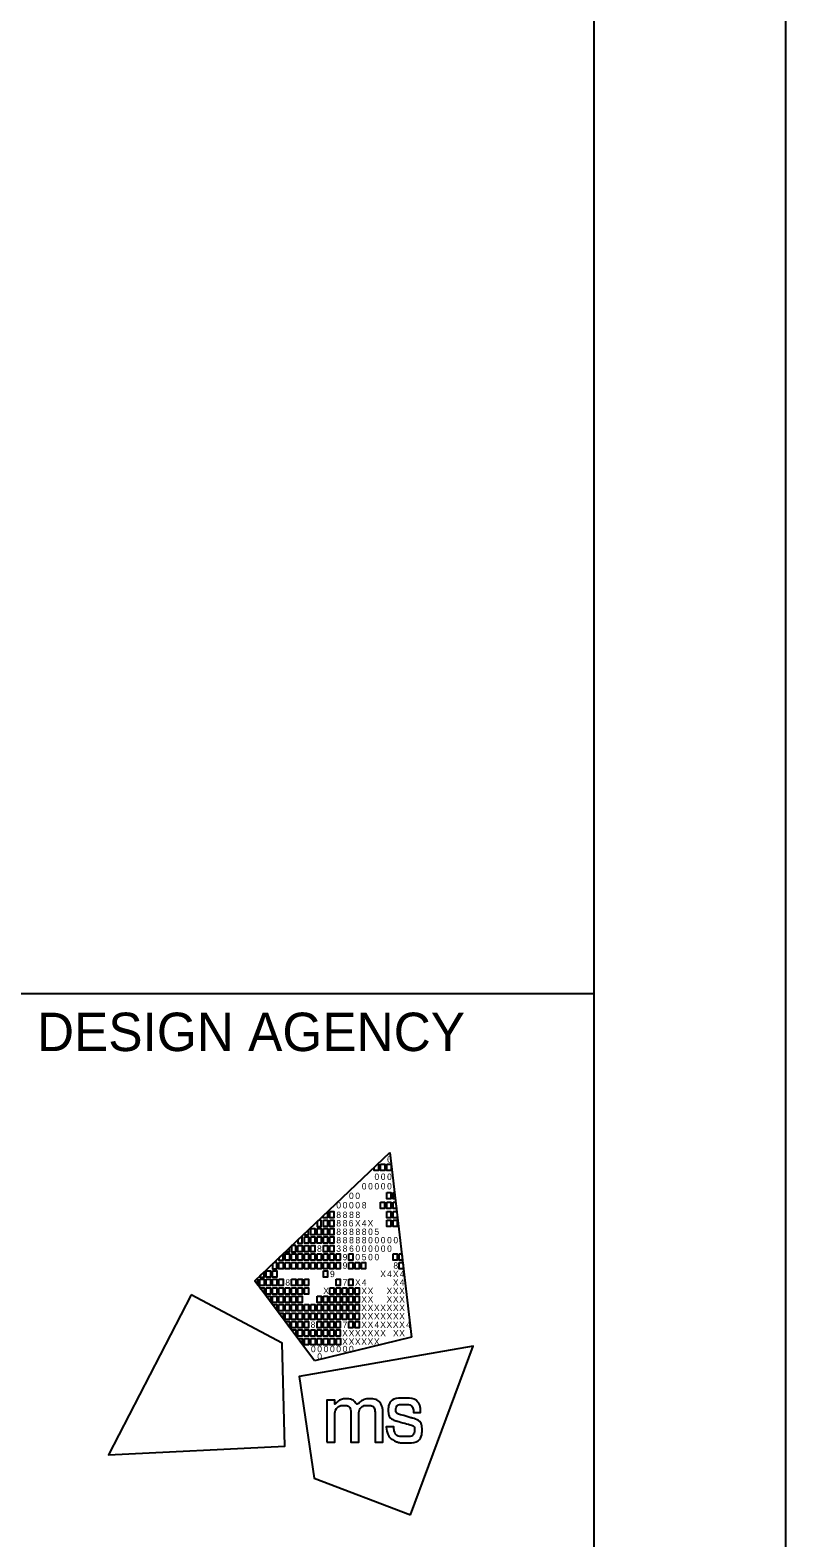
# Model space of a CAD drawing. Extents: x 0 to 34, y -1.2 to 22.
# Drawn here: x 32.032 to 34, y 3.582 to 7.509 of the extents above; entities that cross this region are included whole.
import ezdxf

# ---------------------------------------------------------------- set-up
doc = ezdxf.new("R2010")
doc.units = 0
for name, color, linetype in [('SH_Border', 7, 'Continuous'), ('SH_Cut_Line', 7, 'Continuous'), ('SH_Data', 7, 'Continuous'), ('SH_Text', 7, 'Continuous')]:
    doc.layers.add(name, color=color, linetype=linetype)

msp = doc.modelspace()

# ---------------------------------------------------------------- linework, layer by layer
at = {"layer": 'SH_Border'}
msp.add_line((32, 5), (33.5, 5), dxfattribs=at)
msp.add_lwpolyline([(1.5, 21.5), (33.5, 21.5), (33.5, 0.5), (1.5, 0.5)], close=True, dxfattribs=at)
at = {"layer": 'SH_Cut_Line'}
msp.add_lwpolyline([(0, 0), (34, 0), (34, 22), (0, 22)], close=True, dxfattribs=at)
at = {"layer": 'SH_Data'}
msp.add_line((32.75, 4), (32.75, 4), dxfattribs=at)
at = {"layer": 'SH_Text'}
for p, q in [((32.6175, 4.2519), (32.9688, 4.5861)), ((32.9688, 4.5861), (32.9688, 4.5861)), ((32.9688, 4.5861), (33.0253, 4.1052)), ((32.773, 4.043), (32.6175, 4.2519)), ((33.0253, 4.1052), (32.773, 4.043))]:
    msp.add_line(p, q, dxfattribs=at)
for points in [[(32.9279, 4.5472), (32.9369, 4.5558), (32.9389, 4.5558), (32.9389, 4.5393), (32.9279, 4.5393)], [(32.9444, 4.5558), (32.9554, 4.5558), (32.9554, 4.5393), (32.9444, 4.5393)], [(32.9609, 4.5558), (32.9719, 4.5558), (32.9719, 4.5393), (32.9609, 4.5393)], [(32.9606, 4.4815), (32.9716, 4.4815), (32.9716, 4.465), (32.9606, 4.465)], [(32.9771, 4.4815), (32.9811, 4.4815), (32.983, 4.465), (32.9771, 4.465)], [(32.9441, 4.4567), (32.9551, 4.4567), (32.9551, 4.4402), (32.9441, 4.4402)], [(32.9606, 4.4567), (32.9716, 4.4567), (32.9716, 4.4402), (32.9606, 4.4402)], [(32.9771, 4.4567), (32.984, 4.4567), (32.9859, 4.4402), (32.9771, 4.4402)], [(32.7953, 4.4211), (32.8064, 4.4316), (32.8064, 4.4154), (32.7953, 4.4154)], [(32.7958, 4.4099), (32.8068, 4.4099), (32.8068, 4.3934), (32.7958, 4.3934)], [(32.8123, 4.4319), (32.8233, 4.4319), (32.8233, 4.4154), (32.8123, 4.4154)], [(32.8123, 4.4099), (32.8233, 4.4099), (32.8233, 4.3934), (32.8123, 4.3934)], [(32.9606, 4.4319), (32.9716, 4.4319), (32.9716, 4.4154), (32.9606, 4.4154)], [(32.9606, 4.4099), (32.9716, 4.4099), (32.9716, 4.3934), (32.9606, 4.3934)], [(32.9771, 4.4319), (32.9869, 4.4319), (32.9881, 4.4218), (32.9881, 4.4154), (32.9771, 4.4154)], [(32.9771, 4.4099), (32.9881, 4.4099), (32.9881, 4.3934), (32.9771, 4.3934)], [(32.7462, 4.3659), (32.7572, 4.3659), (32.7572, 4.3494), (32.7462, 4.3494)], [(32.7627, 4.3879), (32.7737, 4.3879), (32.7737, 4.3714), (32.7627, 4.3714)], [(32.7627, 4.3659), (32.7737, 4.3659), (32.7737, 4.3494), (32.7627, 4.3494)], [(32.7793, 4.3879), (32.7903, 4.3879), (32.7903, 4.3714), (32.7793, 4.3714)], [(32.7793, 4.3659), (32.7903, 4.3659), (32.7903, 4.3494), (32.7793, 4.3494)], [(32.7958, 4.3879), (32.8068, 4.3879), (32.8068, 4.3714), (32.7958, 4.3714)], [(32.7958, 4.3659), (32.8068, 4.3659), (32.8068, 4.3494), (32.7958, 4.3494)], [(32.8123, 4.3879), (32.8233, 4.3879), (32.8233, 4.3714), (32.8123, 4.3714)], [(32.8123, 4.3659), (32.8233, 4.3659), (32.8233, 4.3494), (32.8123, 4.3494)], [(32.6967, 4.3218), (32.7077, 4.3218), (32.7077, 4.3053), (32.6967, 4.3053)], [(32.7132, 4.3218), (32.7242, 4.3218), (32.7242, 4.3053), (32.7132, 4.3053)], [(32.7297, 4.3439), (32.7407, 4.3439), (32.7407, 4.3273), (32.7297, 4.3273)], [(32.7297, 4.3218), (32.7407, 4.3218), (32.7407, 4.3053), (32.7297, 4.3053)], [(32.7462, 4.3439), (32.7572, 4.3439), (32.7572, 4.3273), (32.7462, 4.3273)], [(32.7462, 4.3218), (32.7572, 4.3218), (32.7572, 4.3053), (32.7462, 4.3053)], [(32.7627, 4.3439), (32.7737, 4.3439), (32.7737, 4.3273), (32.7627, 4.3273)], [(32.7627, 4.3218), (32.7737, 4.3218), (32.7737, 4.3053), (32.7627, 4.3053)], [(32.7793, 4.3218), (32.7903, 4.3218), (32.7903, 4.3053), (32.7793, 4.3053)], [(32.7958, 4.3439), (32.8068, 4.3439), (32.8068, 4.3273), (32.7958, 4.3273)], [(32.7958, 4.3218), (32.8068, 4.3218), (32.8068, 4.3053), (32.7958, 4.3053)], [(32.8123, 4.3439), (32.8233, 4.3439), (32.8233, 4.3273), (32.8123, 4.3273)], [(32.8123, 4.3218), (32.8233, 4.3218), (32.8233, 4.3053), (32.8123, 4.3053)], [(32.8288, 4.3218), (32.8398, 4.3218), (32.8398, 4.3053), (32.8288, 4.3053)], [(32.8618, 4.3218), (32.8728, 4.3218), (32.8728, 4.3053), (32.8618, 4.3053)], [(32.9771, 4.3218), (32.9881, 4.3218), (32.9881, 4.3053), (32.9771, 4.3053)], [(32.9935, 4.3218), (32.9998, 4.3218), (33.0018, 4.3053), (32.9935, 4.3053)], [(32.6802, 4.2998), (32.6912, 4.2998), (32.6912, 4.2833), (32.6802, 4.2833)], [(32.6967, 4.2998), (32.7077, 4.2998), (32.7077, 4.2833), (32.6967, 4.2833)], [(32.7132, 4.2998), (32.7242, 4.2998), (32.7242, 4.2833), (32.7132, 4.2833)], [(32.7297, 4.2998), (32.7407, 4.2998), (32.7407, 4.2833), (32.7297, 4.2833)], [(32.7462, 4.2998), (32.7572, 4.2998), (32.7572, 4.2833), (32.7462, 4.2833)], [(32.7627, 4.2998), (32.7737, 4.2998), (32.7737, 4.2833), (32.7627, 4.2833)], [(32.7793, 4.2998), (32.7903, 4.2998), (32.7903, 4.2833), (32.7793, 4.2833)], [(32.7958, 4.2998), (32.8068, 4.2998), (32.8068, 4.2833), (32.7958, 4.2833)], [(32.8123, 4.2998), (32.8233, 4.2998), (32.8233, 4.2833), (32.8123, 4.2833)], [(32.8288, 4.2998), (32.8398, 4.2998), (32.8398, 4.2833), (32.8288, 4.2833)], [(32.8618, 4.2998), (32.8728, 4.2998), (32.8728, 4.2833), (32.8618, 4.2833)], [(32.8783, 4.2998), (32.8893, 4.2998), (32.8893, 4.2833), (32.8783, 4.2833)], [(32.8947, 4.2998), (32.9057, 4.2998), (32.9057, 4.2833), (32.8947, 4.2833)], [(32.9935, 4.2998), (33.0024, 4.2998), (33.0044, 4.2833), (32.9935, 4.2833)], [(32.6306, 4.2558), (32.6416, 4.2558), (32.6416, 4.2393), (32.6306, 4.2393)], [(32.6471, 4.2778), (32.6581, 4.2778), (32.6581, 4.2613), (32.6471, 4.2613)], [(32.6471, 4.2558), (32.6581, 4.2558), (32.6581, 4.2393), (32.6471, 4.2393)], [(32.6637, 4.2778), (32.6747, 4.2778), (32.6747, 4.2613), (32.6637, 4.2613)], [(32.6637, 4.2558), (32.6747, 4.2558), (32.6747, 4.2393), (32.6637, 4.2393)], [(32.6802, 4.2558), (32.6912, 4.2558), (32.6912, 4.2393), (32.6802, 4.2393)], [(32.7132, 4.2558), (32.7242, 4.2558), (32.7242, 4.2393), (32.7132, 4.2393)], [(32.7297, 4.2558), (32.7407, 4.2558), (32.7407, 4.2393), (32.7297, 4.2393)], [(32.7462, 4.2558), (32.7572, 4.2558), (32.7572, 4.2393), (32.7462, 4.2393)], [(32.7958, 4.2778), (32.8068, 4.2778), (32.8068, 4.2613), (32.7958, 4.2613)], [(32.8288, 4.2558), (32.8398, 4.2558), (32.8398, 4.2393), (32.8288, 4.2393)], [(32.8618, 4.2558), (32.8728, 4.2558), (32.8728, 4.2393), (32.8618, 4.2393)], [(32.6306, 4.2338), (32.6416, 4.2338), (32.6416, 4.22)], [(32.6471, 4.2338), (32.6581, 4.2338), (32.6581, 4.2173), (32.6471, 4.2173)], [(32.6471, 4.2117), (32.6581, 4.2117), (32.6581, 4.198)], [(32.6637, 4.2338), (32.6747, 4.2338), (32.6747, 4.2173), (32.6637, 4.2173)], [(32.6637, 4.2117), (32.6747, 4.2117), (32.6747, 4.1952), (32.6637, 4.1952)], [(32.6802, 4.2338), (32.6912, 4.2338), (32.6912, 4.2173), (32.6802, 4.2173)], [(32.6802, 4.2117), (32.6912, 4.2117), (32.6912, 4.1952), (32.6802, 4.1952)], [(32.6967, 4.2338), (32.7077, 4.2338), (32.7077, 4.2173), (32.6967, 4.2173)], [(32.6967, 4.2117), (32.7077, 4.2117), (32.7077, 4.1952), (32.6967, 4.1952)], [(32.7132, 4.2338), (32.7242, 4.2338), (32.7242, 4.2173), (32.7132, 4.2173)], [(32.7132, 4.2117), (32.7242, 4.2117), (32.7242, 4.1952), (32.7132, 4.1952)], [(32.7297, 4.2338), (32.7407, 4.2338), (32.7407, 4.2173), (32.7297, 4.2173)], [(32.7297, 4.2117), (32.7407, 4.2117), (32.7407, 4.1952), (32.7297, 4.1952)], [(32.7462, 4.2338), (32.7572, 4.2338), (32.7572, 4.2173), (32.7462, 4.2173)], [(32.7793, 4.2117), (32.7903, 4.2117), (32.7903, 4.1952), (32.7793, 4.1952)], [(32.7958, 4.2117), (32.8068, 4.2117), (32.8068, 4.1952), (32.7958, 4.1952)], [(32.8123, 4.2338), (32.8233, 4.2338), (32.8233, 4.2173), (32.8123, 4.2173)], [(32.8123, 4.2117), (32.8233, 4.2117), (32.8233, 4.1952), (32.8123, 4.1952)], [(32.8288, 4.2338), (32.8398, 4.2338), (32.8398, 4.2173), (32.8288, 4.2173)], [(32.8288, 4.2117), (32.8398, 4.2117), (32.8398, 4.1952), (32.8288, 4.1952)], [(32.8453, 4.2338), (32.8563, 4.2338), (32.8563, 4.2173), (32.8453, 4.2173)], [(32.8453, 4.2117), (32.8563, 4.2117), (32.8563, 4.1952), (32.8453, 4.1952)], [(32.8618, 4.2338), (32.8728, 4.2338), (32.8728, 4.2173), (32.8618, 4.2173)], [(32.8618, 4.2117), (32.8728, 4.2117), (32.8728, 4.1952), (32.8618, 4.1952)], [(32.8783, 4.2338), (32.8893, 4.2338), (32.8893, 4.2173), (32.8783, 4.2173)], [(32.8783, 4.2117), (32.8893, 4.2117), (32.8893, 4.1952), (32.8783, 4.1952)], [(32.6637, 4.1897), (32.6747, 4.1897), (32.6747, 4.176)], [(32.6747, 4.1897), (32.6747, 4.1897), (32.6747, 4.1897)], [(32.6802, 4.1897), (32.6912, 4.1897), (32.6912, 4.1732), (32.6802, 4.1732)], [(32.6802, 4.1677), (32.6912, 4.1677), (32.6912, 4.154)], [(32.6967, 4.1897), (32.7077, 4.1897), (32.7077, 4.1732), (32.6967, 4.1732)], [(32.6967, 4.1677), (32.7077, 4.1677), (32.7077, 4.1512), (32.6967, 4.1512)], [(32.7132, 4.1897), (32.7242, 4.1897), (32.7242, 4.1732), (32.7132, 4.1732)], [(32.7132, 4.1677), (32.7242, 4.1677), (32.7242, 4.1512), (32.7132, 4.1512)], [(32.7297, 4.1897), (32.7407, 4.1897), (32.7407, 4.1732), (32.7297, 4.1732)], [(32.7297, 4.1677), (32.7407, 4.1677), (32.7407, 4.1512), (32.7297, 4.1512)], [(32.7462, 4.1897), (32.7572, 4.1897), (32.7572, 4.1732), (32.7462, 4.1732)], [(32.7462, 4.1677), (32.7572, 4.1677), (32.7572, 4.1512), (32.7462, 4.1512)], [(32.7627, 4.1897), (32.7737, 4.1897), (32.7737, 4.1732), (32.7627, 4.1732)], [(32.7627, 4.1677), (32.7737, 4.1677), (32.7737, 4.1512), (32.7627, 4.1512)], [(32.7793, 4.1897), (32.7903, 4.1897), (32.7903, 4.1732), (32.7793, 4.1732)], [(32.7793, 4.1677), (32.7903, 4.1677), (32.7903, 4.1512), (32.7793, 4.1512)], [(32.7958, 4.1897), (32.8068, 4.1897), (32.8068, 4.1732), (32.7958, 4.1732)], [(32.7958, 4.1677), (32.8068, 4.1677), (32.8068, 4.1512), (32.7958, 4.1512)], [(32.8123, 4.1897), (32.8233, 4.1897), (32.8233, 4.1732), (32.8123, 4.1732)], [(32.8123, 4.1677), (32.8233, 4.1677), (32.8233, 4.1512), (32.8123, 4.1512)], [(32.8288, 4.1897), (32.8398, 4.1897), (32.8398, 4.1732), (32.8288, 4.1732)], [(32.8288, 4.1677), (32.8398, 4.1677), (32.8398, 4.1512), (32.8288, 4.1512)], [(32.8453, 4.1897), (32.8563, 4.1897), (32.8563, 4.1732), (32.8453, 4.1732)], [(32.8453, 4.1677), (32.8563, 4.1677), (32.8563, 4.1512), (32.8453, 4.1512)], [(32.8618, 4.1897), (32.8728, 4.1897), (32.8728, 4.1732), (32.8618, 4.1732)], [(32.8618, 4.1677), (32.8728, 4.1677), (32.8728, 4.1512), (32.8618, 4.1512)], [(32.8783, 4.1897), (32.8893, 4.1897), (32.8893, 4.1732), (32.8783, 4.1732)], [(32.8783, 4.1677), (32.8893, 4.1677), (32.8893, 4.1512), (32.8783, 4.1512)], [(32.7077, 4.1305), (32.6965, 4.1457), (32.7077, 4.1457)], [(32.7132, 4.1457), (32.7242, 4.1457), (32.7242, 4.1292), (32.7132, 4.1292)], [(32.724, 4.1082), (32.7132, 4.1237), (32.7242, 4.1237)], [(32.7297, 4.1457), (32.7407, 4.1457), (32.7407, 4.1292), (32.7297, 4.1292)], [(32.7297, 4.1237), (32.7407, 4.1237), (32.7407, 4.1072), (32.7297, 4.1072)], [(32.7462, 4.1457), (32.7572, 4.1457), (32.7572, 4.1292), (32.7462, 4.1292)], [(32.7462, 4.1237), (32.7572, 4.1237), (32.7572, 4.1072), (32.7462, 4.1072)], [(32.7627, 4.1237), (32.7737, 4.1237), (32.7737, 4.1072), (32.7627, 4.1072)], [(32.7793, 4.1457), (32.7903, 4.1457), (32.7903, 4.1292), (32.7793, 4.1292)], [(32.7793, 4.1237), (32.7903, 4.1237), (32.7903, 4.1072), (32.7793, 4.1072)], [(32.7958, 4.1457), (32.8068, 4.1457), (32.8068, 4.1292), (32.7958, 4.1292)], [(32.7958, 4.1237), (32.8068, 4.1237), (32.8068, 4.1072), (32.7958, 4.1072)], [(32.8123, 4.1457), (32.8233, 4.1457), (32.8233, 4.1292), (32.8123, 4.1292)], [(32.8123, 4.1237), (32.8233, 4.1237), (32.8233, 4.1072), (32.8123, 4.1072)], [(32.8288, 4.1457), (32.8398, 4.1457), (32.8398, 4.1292), (32.8288, 4.1292)], [(32.8288, 4.1237), (32.8398, 4.1237), (32.8398, 4.1072), (32.8288, 4.1072)], [(32.8618, 4.1457), (32.8728, 4.1457), (32.8728, 4.1292), (32.8618, 4.1292)], [(32.8783, 4.1457), (32.8893, 4.1457), (32.8893, 4.1292), (32.8783, 4.1292)], [(32.7302, 4.1017), (32.7407, 4.1017), (32.7408, 4.0875)], [(32.7463, 4.1017), (32.7573, 4.1017), (32.7573, 4.0852), (32.7463, 4.0852)], [(32.763, 4.1017), (32.774, 4.1017), (32.774, 4.0852), (32.763, 4.0852)], [(32.7794, 4.1017), (32.7904, 4.1017), (32.7904, 4.0852), (32.7794, 4.0852)], [(32.796, 4.1017), (32.807, 4.1017), (32.807, 4.0852), (32.796, 4.0852)], [(32.8129, 4.1017), (32.8239, 4.1017), (32.8239, 4.0851), (32.8129, 4.0851)], [(32.8296, 4.1017), (32.8406, 4.1017), (32.8406, 4.0851), (32.8296, 4.0851)]]:
    msp.add_lwpolyline(points, close=True, dxfattribs=at)
for points in [[(32.7903, 4.4099), (32.7836, 4.4099), (32.7793, 4.4058), (32.7793, 4.3934), (32.7903, 4.3934), (32.7903, 4.4099)], [(32.7407, 4.3691), (32.7297, 4.3587), (32.7297, 4.3494), (32.7407, 4.3494), (32.7407, 4.3691)], [(32.7572, 4.3849), (32.7462, 4.3744), (32.7462, 4.3714), (32.7572, 4.3714), (32.7572, 4.3849)], [(32.6912, 4.322), (32.6802, 4.3115), (32.6802, 4.3053), (32.6912, 4.3053), (32.6912, 4.322)], [(32.7077, 4.3377), (32.6968, 4.3273), (32.7077, 4.3273), (32.7077, 4.3377)], [(32.7242, 4.3439), (32.7141, 4.3439), (32.7132, 4.343), (32.7132, 4.3273), (32.7242, 4.3273), (32.7242, 4.3439)], [(32.6747, 4.2998), (32.6679, 4.2998), (32.6637, 4.2958), (32.6637, 4.2833), (32.6747, 4.2833), (32.6747, 4.2998)], [(32.6251, 4.2558), (32.6216, 4.2558), (32.6175, 4.2519), (32.6251, 4.2417), (32.6251, 4.2558)], [(32.6416, 4.2749), (32.6306, 4.2644), (32.6306, 4.2613), (32.6416, 4.2613), (32.6416, 4.2749)], [(32.4512, 4.2149), (32.2359, 3.7988), (32.6956, 3.8215), (32.6884, 4.0892), (32.4512, 4.2149)], [(33.0229, 3.6422), (33.1859, 4.0814), (32.7324, 4.0029), (32.7722, 3.7381), (33.0229, 3.6422)]]:
    msp.add_lwpolyline(points, dxfattribs=at)
for points in [[(32.8048, 3.8315), (32.8048, 3.8315), (32.8048, 3.9409), (32.8048, 3.9409), (32.8048, 3.9409), (32.8255, 3.9409), (32.8255, 3.9409), (32.8255, 3.9409), (32.8255, 3.9297), (32.8255, 3.9297), (32.8346, 3.9399), (32.8457, 3.9445), (32.8555, 3.9445), (32.8688, 3.9445), (32.8791, 3.9372), (32.8837, 3.9266), (32.8915, 3.9381), (32.905, 3.9446), (32.9166, 3.9446), (32.9325, 3.9446), (32.9451, 3.935), (32.9494, 3.9213), (32.9494, 3.9212), (32.9494, 3.9212), (32.9494, 3.9212), (32.9501, 3.919), (32.9506, 3.9172), (32.9506, 3.9071), (32.9506, 3.9071), (32.9506, 3.8314), (32.9506, 3.8314), (32.9506, 3.8314), (32.9303, 3.8314), (32.9303, 3.8314), (32.9303, 3.8314), (32.9303, 3.9048), (32.9303, 3.9048), (32.9303, 3.9201), (32.9219, 3.9274), (32.911, 3.9274), (32.8995, 3.9274), (32.8879, 3.9171), (32.8879, 3.9001), (32.8879, 3.9001), (32.8879, 3.8315), (32.8879, 3.8315), (32.8879, 3.8315), (32.8674, 3.8315), (32.8674, 3.8315), (32.8674, 3.8315), (32.8674, 3.9059), (32.8674, 3.9059), (32.8674, 3.9203), (32.8588, 3.9274), (32.8496, 3.9274), (32.8384, 3.9274), (32.8254, 3.917), (32.8254, 3.8962), (32.8254, 3.8962), (32.8254, 3.8315), (32.8254, 3.8315), (32.8254, 3.8315), (32.8048, 3.8315), (32.8048, 3.8315)], [(32.9595, 3.8709), (32.9595, 3.8709), (32.9595, 3.8717), (32.9595, 3.8717), (32.9595, 3.8717), (32.9603, 3.8717), (32.9603, 3.8717), (32.9603, 3.8717), (32.9783, 3.8717), (32.9783, 3.8717), (32.9783, 3.8717), (32.9789, 3.8717), (32.9789, 3.8717), (32.9789, 3.8717), (32.979, 3.871), (32.979, 3.871), (32.9803, 3.8554), (32.9887, 3.846), (33.009, 3.846), (33.0273, 3.846), (33.0333, 3.8554), (33.0333, 3.8631), (33.0333, 3.8732), (33.0256, 3.8758), (33.0175, 3.878), (33.0175, 3.878), (32.987, 3.8867), (32.987, 3.8867), (32.972, 3.8909), (32.9648, 3.9019), (32.9648, 3.9142), (32.9648, 3.9303), (32.9768, 3.9462), (33.0052, 3.9462), (33.0348, 3.9462), (33.0489, 3.9285), (33.0489, 3.9095), (33.0489, 3.9095), (33.0489, 3.9087), (33.0489, 3.9087), (33.0489, 3.9087), (33.0482, 3.9087), (33.0482, 3.9087), (33.0482, 3.9087), (33.0312, 3.9087), (33.0312, 3.9087), (33.0312, 3.9087), (33.0305, 3.9087), (33.0305, 3.9087), (33.0305, 3.9087), (33.0305, 3.9094), (33.0305, 3.9094), (33.0301, 3.9208), (33.0226, 3.93), (33.0056, 3.93), (32.9891, 3.93), (32.9843, 3.9218), (32.9843, 3.9157), (32.9843, 3.9108), (32.9869, 3.9059), (32.9959, 3.9033), (32.9959, 3.9033), (33.0255, 3.8948), (33.0255, 3.8948), (33.0462, 3.8889), (33.0527, 3.8777), (33.0527, 3.8639), (33.0527, 3.8462), (33.041, 3.8298), (33.0087, 3.8298), (32.9952, 3.8298), (32.9877, 3.8321), (32.9823, 3.8348), (32.969, 3.8414), (32.9609, 3.8536), (32.9595, 3.8709)]]:
    msp.add_open_spline(points, degree=3, dxfattribs=at)

# ---------------------------------------------------------------- texts
at = {"layer": 'SH_Data'}
msp.add_text('DESIGN AGENCY', height=0.1, dxfattribs=at).set_placement((32.05, 4.85))
at = {"layer": 'SH_Text'}
for s, p in [('0', (32.9617, 4.5597)), ('0', (32.9288, 4.5145)), ('0', (32.9452, 4.5145)), ('0', (32.9617, 4.5145)), ('0', (32.8625, 4.465)), ('0', (32.879, 4.465)), ('0', (32.8958, 4.4897)), ('0', (32.9123, 4.4897)), ('0', (32.9288, 4.4897)), ('0', (32.9452, 4.4897)), ('0', (32.9617, 4.4897)), ('0', (32.8295, 4.4402)), ('0', (32.846, 4.4402)), ('0', (32.8625, 4.4402)), ('0', (32.879, 4.4402)), ('8', (32.8958, 4.4402)), ('8', (32.8295, 4.4154)), ('8', (32.8295, 4.3934)), ('8', (32.846, 4.4154)), ('8', (32.846, 4.3934)), ('6', (32.8618, 4.3934)), ('8', (32.8628, 4.4154)), ('X', (32.8781, 4.3934)), ('8', (32.8793, 4.4154)), ('4', (32.8958, 4.3934)), ('X', (32.911, 4.3934)), ('8', (32.8295, 4.3713)), ('8', (32.8295, 4.3494)), ('8', (32.846, 4.3713)), ('8', (32.846, 4.3494)), ('8', (32.8628, 4.3713)), ('8', (32.8628, 4.3494)), ('8', (32.8794, 4.3713)), ('8', (32.8794, 4.3494)), ('8', (32.8958, 4.3713)), ('8', (32.8958, 4.3494)), ('0', (32.9123, 4.3713)), ('0', (32.9123, 4.3494)), ('5', (32.9287, 4.3713)), ('0', (32.9288, 4.3494)), ('0', (32.9452, 4.3494)), ('0', (32.9617, 4.3494)), ('0', (32.9782, 4.3494)), ('8', (32.7793, 4.3273)), ('3', (32.8295, 4.3273)), ('8', (32.846, 4.3273)), ('9', (32.846, 4.3053)), ('6', (32.8629, 4.3273)), ('0', (32.879, 4.3053)), ('0', (32.8793, 4.3273)), ('5', (32.8957, 4.3053)), ('0', (32.8958, 4.3273)), ('0', (32.9123, 4.3273)), ('0', (32.9123, 4.3053)), ('0', (32.9288, 4.3273)), ('0', (32.9288, 4.3053)), ('0', (32.9452, 4.3273)), ('0', (32.9617, 4.3273)), ('9', (32.846, 4.2833)), ('8', (32.9781, 4.2833)), ('8', (32.6967, 4.2393)), ('9', (32.813, 4.2613)), ('7', (32.846, 4.2393)), ('X', (32.8781, 4.2393)), ('4', (32.8958, 4.2393)), ('X', (32.9439, 4.2613)), ('4', (32.9617, 4.2613)), ('X', (32.9769, 4.2613)), ('X', (32.9769, 4.2393)), ('4', (32.9946, 4.2613)), ('4', (32.9946, 4.2393)), ('X', (32.7955, 4.2173)), ('X', (32.8945, 4.2173)), ('X', (32.8945, 4.1952)), ('X', (32.911, 4.2173)), ('X', (32.911, 4.1952)), ('X', (32.9604, 4.2173)), ('X', (32.9604, 4.1952)), ('X', (32.9769, 4.2173)), ('X', (32.9769, 4.1952)), ('X', (32.9933, 4.2173)), ('X', (32.9933, 4.1952)), ('X', (32.8945, 4.1732)), ('X', (32.8945, 4.1512)), ('X', (32.911, 4.1732)), ('X', (32.911, 4.1512)), ('X', (32.9274, 4.1732)), ('X', (32.9274, 4.1512)), ('X', (32.9439, 4.1732)), ('X', (32.9439, 4.1512)), ('X', (32.9604, 4.1732)), ('X', (32.9604, 4.1512)), ('X', (32.9769, 4.1732)), ('X', (32.9769, 4.1512)), ('X', (32.9933, 4.1732)), ('X', (32.9933, 4.1512)), ('8', (32.7627, 4.1292)), ('X', (32.8447, 4.1072)), ('7', (32.846, 4.1292)), ('X', (32.8616, 4.1072)), ('X', (32.878, 4.1072)), ('X', (32.8945, 4.1292)), ('X', (32.8945, 4.1072)), ('X', (32.911, 4.1292)), ('X', (32.911, 4.1072)), ('X', (32.9274, 4.1072)), ('4', (32.9288, 4.1292)), ('X', (32.9439, 4.1292)), ('X', (32.9439, 4.1072)), ('X', (32.9604, 4.1292)), ('X', (32.9769, 4.1292)), ('X', (32.9771, 4.1072)), ('X', (32.9933, 4.1292)), ('X', (32.9933, 4.1072)), ('4', (33.0111, 4.1292)), ('X', (32.8447, 4.0851)), ('X', (32.8616, 4.0851)), ('X', (32.878, 4.0851)), ('X', (32.8945, 4.0851)), ('X', (32.911, 4.0851)), ('X', (32.9274, 4.0851)), ('0', (32.7634, 4.0659)), ('0', (32.7799, 4.0659)), ('0', (32.7799, 4.0467)), ('0', (32.7965, 4.0659)), ('0', (32.813, 4.0659)), ('0', (32.8295, 4.0659)), ('0', (32.846, 4.0659)), ('0', (32.8625, 4.0659))]:
    msp.add_text(s, height=0.0165, rotation=360, dxfattribs=at).set_placement(p)

doc.saveas('drawing.dxf')
